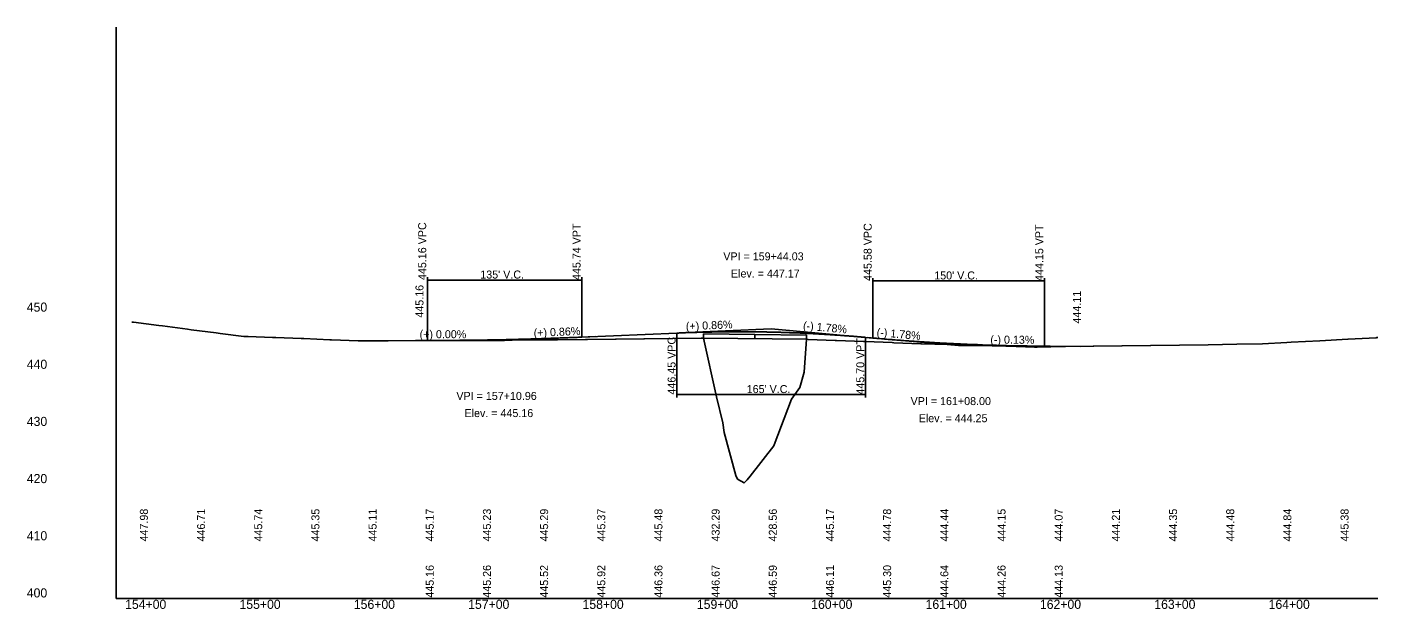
# Model space of a CAD drawing. Extents: x 151 to 1332, y 337 to 846.
import ezdxf

# ---------------------------------------------------------------- set-up
doc = ezdxf.new("R2010")
doc.units = 0
for name, color, linetype in [('Default', 7, 'Continuous'), ('RD_DDB_ElevTX', 7, 'Continuous'), ('RD_DDB_GradeTX', 7, 'Continuous'), ('RD_DDB_Profile_EX', 7, 'Continuous'), ('RD_DDB_Profile_Lbl', 7, 'Continuous'), ('RD_DDB_Profile_PR', 7, 'Continuous'), ('RD_DDB_StaTX', 7, 'Continuous'), ('RD_DDB_StripGrade', 7, 'Continuous'), ('RD_DDB_VCLbl', 7, 'Continuous'), ('RD_GPK_Profile_Cell', 7, 'Continuous')]:
    doc.layers.add(name, color=color, linetype=linetype)

msp = doc.modelspace()

# ---------------------------------------------------------------- linework, layer by layer
at = {"layer": 'Default'}
for p, q in [((742.4, 574.2), (742.4, 577.9)), ((787.4, 577.5), (742.4, 577.9)), ((832.4, 573.3), (742.4, 574.2)), ((787.4, 573.7), (787.4, 577.5)), ((832.4, 577), (787.4, 577.5)), ((832.4, 573.3), (832.4, 577))]:
    msp.add_line(p, q, dxfattribs=at)
at = {"layer": 'RD_DDB_GradeTX'}
for p, q in [((721.6, 578.8), (801.5, 582.3)), ((881.2, 575.2), (801.5, 582.3)), ((497.5, 572.2), (568.4, 572.2)), ((648.3, 575.7), (568.4, 572.2)), ((885.8, 574.8), (965.5, 567.7)), ((1045.5, 567.2), (965.5, 567.7))]:
    msp.add_line(p, q, dxfattribs=at)
at = {"layer": 'RD_DDB_Profile_EX'}
msp.add_lwpolyline([(242.5, 588.2), (243.9, 588.1), (266.2, 585.2), (269.2, 584.9), (291.2, 582), (294.4, 581.6), (316.2, 578.9), (319.6, 578.4), (340.5, 575.8), (344.1, 575.6), (365.5, 574.8), (368.5, 574.7), (390.5, 573.9), (392.8, 573.8), (415.5, 572.9), (417, 572.8), (440.5, 571.9), (441.3, 571.9), (465.5, 572), (466.5, 572), (490.5, 572.2), (491.7, 572.2), (515.5, 572.3), (516.8, 572.3), (539.9, 572.4), (563.6, 572.6), (564.8, 572.6), (588.7, 572.8), (589.8, 572.8), (613.9, 572.9), (614.8, 572.9), (639.1, 573.1), (639.8, 573.1), (640.3, 573.1), (641, 573.1), (665.3, 573.4), (665.9, 573.4), (690.3, 573.6), (690.8, 573.6), (715.3, 573.9), (715.7, 573.9), (740.3, 574.2), (742.4, 574.2), (753.9, 522.8), (759.3, 500.2), (760.4, 491.7), (770.6, 454.2), (772.2, 450.9), (777.9, 447.6), (780.6, 450.4), (783.3, 453.6), (803.9, 480), (804.3, 480.9), (819.4, 520.9), (826.6, 531), (830.4, 544.6), (832.4, 573.3), (833.8, 573.2), (857.4, 572.3), (858.8, 572.2), (882.4, 571.3), (883.8, 571.2), (907.4, 570.3), (908.9, 570.2), (932.4, 569.3), (932.9, 569.3), (956.5, 568.6), (957.9, 568.6), (981.6, 567.9), (982.9, 567.9), (1006.8, 567.2), (1007.9, 567.2), (1031.9, 566.5), (1032.9, 566.5), (1033.2, 566.5), (1034.2, 566.5), (1058.2, 566.8), (1059, 566.8), (1083.2, 567.1), (1083.7, 567.2), (1108.2, 567.5), (1108.5, 567.5), (1133.2, 567.9), (1133.7, 567.9), (1158.7, 568.2), (1183.7, 568.5), (1208.7, 568.9), (1231.3, 569.2), (1252.4, 570.3), (1256.3, 570.6), (1281.3, 571.9), (1305.9, 573.3), (1306.3, 573.3), (1330.7, 574.6), (1331.3, 574.7), (1332.2, 574.7)], dxfattribs=at)
at = {"layer": 'RD_DDB_Profile_PR'}
for p, q in [((497.5, 572.2), (500.9, 572.2)), ((635.9, 575.1), (719, 578.7)), ((884, 574.9), (890.5, 574.3)), ((1040.5, 567.2), (1072.5, 567))]:
    msp.add_line(p, q, dxfattribs=at)
for points in [[(719, 578.7), (722.3, 578.8), (725.6, 579), (728.9, 579.1), (732.2, 579.2), (735.5, 579.3), (738.8, 579.4), (742.1, 579.5), (745.4, 579.6), (748.7, 579.6), (752, 579.7), (755.3, 579.7), (758.6, 579.8), (761.9, 579.8), (765.2, 579.8), (768.5, 579.9), (771.8, 579.9), (775.1, 579.9), (778.4, 579.9), (781.7, 579.8), (785, 579.8), (788.3, 579.8), (791.6, 579.7), (794.9, 579.7), (798.2, 579.6), (801.5, 579.5), (804.8, 579.5), (808.1, 579.4), (811.4, 579.3), (814.7, 579.2), (818, 579), (821.3, 578.9), (824.6, 578.8), (827.9, 578.7), (831.2, 578.5), (834.5, 578.3), (837.8, 578.2), (841.1, 578), (844.4, 577.8), (847.7, 577.6), (851, 577.4), (854.3, 577.2), (857.6, 577), (860.9, 576.8), (864.2, 576.5), (867.5, 576.3), (870.8, 576), (874.1, 575.8), (877.4, 575.5), (880.7, 575.2), (884, 574.9)], [(500.9, 572.2), (503.6, 572.2), (506.3, 572.2), (509, 572.2), (511.7, 572.2), (514.4, 572.2), (517.1, 572.3), (519.8, 572.3), (522.5, 572.3), (525.2, 572.3), (527.9, 572.3), (530.6, 572.4), (533.3, 572.4), (536, 572.4), (538.7, 572.4), (541.4, 572.5), (544.1, 572.5), (546.8, 572.6), (549.5, 572.6), (552.2, 572.6), (554.9, 572.7), (557.6, 572.7), (560.3, 572.8), (563, 572.8), (565.7, 572.9), (568.4, 572.9), (571.1, 573), (573.8, 573.1), (576.5, 573.1), (579.2, 573.2), (581.9, 573.3), (584.6, 573.3), (587.3, 573.4), (590, 573.5), (592.7, 573.6), (595.4, 573.6), (598.1, 573.7), (600.8, 573.8), (603.5, 573.9), (606.2, 574), (608.9, 574.1), (611.6, 574.2), (614.3, 574.3), (617, 574.4), (619.7, 574.5), (622.4, 574.6), (625.1, 574.7), (627.8, 574.8), (630.5, 574.9), (633.2, 575), (635.9, 575.1)], [(890.5, 574.3), (893.5, 574.1), (896.5, 573.8), (899.5, 573.6), (902.5, 573.3), (905.5, 573.1), (908.5, 572.8), (911.5, 572.6), (914.5, 572.4), (917.5, 572.1), (920.5, 571.9), (923.5, 571.7), (926.5, 571.5), (929.5, 571.3), (932.5, 571.1), (935.5, 570.9), (938.5, 570.7), (941.5, 570.5), (944.5, 570.3), (947.5, 570.2), (950.5, 570), (953.5, 569.8), (956.5, 569.7), (959.5, 569.5), (962.5, 569.4), (965.5, 569.2), (968.5, 569.1), (971.5, 569), (974.5, 568.8), (977.5, 568.7), (980.5, 568.6), (983.5, 568.5), (986.5, 568.3), (989.5, 568.2), (992.5, 568.1), (995.5, 568), (998.5, 568), (1001.5, 567.9), (1004.5, 567.8), (1007.5, 567.7), (1010.5, 567.6), (1013.5, 567.6), (1016.5, 567.5), (1019.5, 567.5), (1022.5, 567.4), (1025.5, 567.4), (1028.5, 567.3), (1031.5, 567.3), (1034.5, 567.2), (1037.5, 567.2), (1040.5, 567.2)]]:
    msp.add_spline(points, degree=3, dxfattribs=at)
at = {"layer": 'RD_DDB_VCLbl'}
for p, q in [((500.9, 627.6), (500.9, 572.2)), ((635.9, 627.6), (635.9, 575.1)), ((890.5, 626.8), (890.5, 574.3)), ((1040.5, 626.8), (1040.5, 567.2)), ((500.9, 625.1), (635.9, 625.1)), ((890.5, 624.3), (1040.5, 624.3)), ((719, 522.4), (719, 578.7)), ((884, 522.4), (884, 574.9)), ((719, 524.9), (884, 524.9))]:
    msp.add_line(p, q, dxfattribs=at)
at = {"layer": 'RD_GPK_Profile_Cell'}
for q in [(228.9, 846.4), (1332.2, 346.4), (228.9, 346.4)]:
    msp.add_line((228.9, 346.4), q, dxfattribs=at)

# ---------------------------------------------------------------- texts
at = {"layer": 'RD_DDB_ElevTX'}
for s, p in [('450', (150.6, 597.4)), ('440', (150.6, 547.4)), ('430', (150.6, 497.4)), ('420', (150.6, 447.4)), ('410', (150.6, 397.4)), ('400', (150.6, 347.4))]:
    msp.add_text(s, height=8, dxfattribs=at).set_placement(p)
at = {"layer": 'RD_DDB_GradeTX'}
msp.add_text('(+) 0.00%', height=7, dxfattribs=at).set_placement((494.1, 574.2))
for s, rotation, p in [('(+) 0.86%', 2.4674, (594, 575.3)), ('(+) 0.86%', 2.4674, (727.1, 581.1)), ('(-) 1.78%', 354.9193, (829.2, 581.8)), ('(-) 1.78%', 354.9193, (893.6, 576.1)), ('(-) 0.13%', 359.6353, (993.2, 569.5))]:
    msp.add_text(s, height=7, rotation=rotation, dxfattribs=at).set_placement(p)
at = {"layer": 'RD_DDB_Profile_Lbl'}
for s, p in [('VPI = 159+44.03', (759.7, 642.3)), ('Elev. = 447.17', (766.4, 627.3)), ('VPI = 157+10.96', (526.3, 520.2)), ('VPI = 161+08.00', (923.5, 515.7)), ('Elev. = 445.16', (533.4, 505.2)), ('Elev. = 444.25', (930.6, 500.7))]:
    msp.add_text(s, height=7, dxfattribs=at).set_placement(p)
for s, p in [('445.16', (497.5, 592.2)), ('444.11', (1072.5, 587))]:
    msp.add_text(s, height=7, rotation=90, dxfattribs=at).set_placement(p)
at = {"layer": 'RD_DDB_StaTX'}
for s, p in [('154+00', (236.6, 337.4)), ('155+00', (336.6, 337.4)), ('156+00', (436.6, 337.4)), ('157+00', (536.6, 337.4)), ('158+00', (636.6, 337.4)), ('159+00', (736.6, 337.4)), ('160+00', (836.6, 337.4)), ('161+00', (936.6, 337.4)), ('162+00', (1036.6, 337.4)), ('163+00', (1136.6, 337.4)), ('164+00', (1236.6, 337.4))]:
    msp.add_text(s, height=8, dxfattribs=at).set_placement(p)
at = {"layer": 'RD_DDB_StripGrade'}
for s, p in [('445.16 VPC', (499.9, 625.1)), ('445.74 VPT', (634.9, 625.1)), ('445.58 VPC', (889.5, 624.3)), ('444.15 VPT', (1039.5, 624.3)), ('446.45 VPC', (718, 524.9)), ('445.70 VPT', (883, 524.9)), ('447.98', (256.5, 396.4)), ('446.71', (306.5, 396.4)), ('445.74', (356.5, 396.4)), ('445.35', (406.5, 396.4)), ('445.11', (456.5, 396.4)), ('445.17', (506.5, 396.4)), ('445.23', (556.5, 396.4)), ('445.29', (606.5, 396.4)), ('445.37', (656.5, 396.4)), ('445.48', (706.5, 396.4)), ('432.29', (756.5, 396.4)), ('428.56', (806.5, 396.4)), ('445.17', (856.5, 396.4)), ('444.78', (906.5, 396.4)), ('444.44', (956.5, 396.4)), ('444.15', (1006.5, 396.4)), ('444.07', (1056.5, 396.4)), ('444.21', (1106.5, 396.4)), ('444.35', (1156.5, 396.4)), ('444.48', (1206.5, 396.4)), ('444.84', (1256.5, 396.4)), ('445.38', (1306.5, 396.4)), ('445.16', (506.5, 347.2)), ('445.26', (556.5, 347.2)), ('445.52', (606.5, 347.2)), ('445.92', (656.5, 347.2)), ('446.36', (706.5, 347.2)), ('446.67', (756.5, 347.2)), ('446.59', (806.5, 347.2)), ('446.11', (856.5, 347.2)), ('445.30', (906.5, 347.2)), ('444.64', (956.5, 347.2)), ('444.26', (1006.5, 347.2)), ('444.13', (1056.5, 347.2))]:
    msp.add_text(s, height=7, rotation=90, dxfattribs=at).set_placement(p)
at = {"layer": 'RD_DDB_VCLbl'}
for s, p in [("135' V.C.", (547.2, 626.4)), ("150' V.C.", (944.2, 625.6)), ("165' V.C.", (780.2, 526.2))]:
    msp.add_text(s, height=7, dxfattribs=at).set_placement(p)
at = {"layer": 'RD_GPK_Profile_Cell'}
for s, p in [('816', (228.9, 346.5)), ('S816', (228.9, 346.5)), ('15371.420000', (228.9, 346.5)), ('400', (228.9, 346.5)), ('50', (228.9, 346.5)), ('10', (228.9, 346.5)), ('NOGAP', (228.9, 346.4))]:
    msp.add_text(s, height=0.00975, dxfattribs=at).set_placement(p)

doc.saveas('drawing.dxf')
